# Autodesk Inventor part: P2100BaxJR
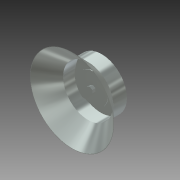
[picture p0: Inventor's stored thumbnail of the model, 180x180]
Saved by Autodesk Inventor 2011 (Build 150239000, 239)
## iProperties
Created: 2014-07
Part Number: P2100BaxJR
Document SubType Name: Modeling
Designer: Evgeny
Density: 1 g/cm^3
Author: Evgeny
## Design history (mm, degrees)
sketch "Эскиз1"
  geometry: L1 (31, 26.833)-(31, -26.833); L2 (-31, -26.833)-(-31, 26.833); C1 r 1.35 at (15, -26); A1 r 41 centre (0, 0) between (31, 26.833) and (-31, 26.833); A2 r 41 centre (0, 0) between (-31, -26.833) and (31, -26.833); 1 further point
  constraints: 4 end point, 4 point on circle, 3 centre point, 1 coincident, 1 parallel
  dimensions: "d1" = 62 distance between parallel lines of L1 L2; "d2" = 31 distance from line of L2 point (0, 0); "d3" = 41 radius of A1; "d4" = 41 radius of A2; "d7" = 2.7 diameter of C1; "d9" = 26 vertical distance of point (0, 0) C1.centre; "d50" = 15 horizontal distance of C1.centre point (0, 0)
extrude "Выдавливание1" new body sketch "Эскиз1" distance "d10" = 1; taper "d11" = 0 deg
sketch "Эскиз2"
  geometry: C1 r 4 at (0, 0); A1 r 41 centre (0, 0) between (31, 26.833) and (-31, 26.833) reference
  constraints: 1 centre point, 1 coincident
  dimensions: "d12" = 8 diameter of C1
extrude "Выдавливание2" join sketch "Эскиз2" distance "d13" = 6; taper "d14" = 0 deg
sketch "Эскиз3"
  geometry: C1 r 4 at (0, 0) reference; C2 r 28 at (0, 0)
  constraints: 1 centre point, 1 coincident
  dimensions: "d15" = 56 diameter of C2
extrude "Выдавливание3" join sketch "Эскиз3" distance "d16" = 1; taper "d17" = 0 deg
sketch "Эскиз4"
  geometry: L1 (5.774, 0)-(2.887, -5); L2 (2.887, -5)-(-2.887, -5); L3 (-2.887, -5)-(-5.774, 0); L4 (-5.774, 0)-(-2.887, 5); L5 (-2.887, 5)-(2.887, 5); L6 (2.887, 5)-(5.774, 0); C1 r 28 at (0, 0) reference; 1 further point
  constraints: 12 end point, 1 coincident, 13 other
  dimensions: "d18" = 10 distance between parallel lines of L2 L5
extrude "Выдавливание4" join sketch "Эскиз4" distance "d19" = 6; taper "d20" = 0 deg
sketch "Эскиз5"
  geometry: C1 r 4 at (0, 0); A1 r 41 centre (0, 0) between (31, 26.833) and (-31, 26.833) reference
  constraints: 1 centre point, 1 coincident
  dimensions: "d21" = 8 diameter of C1
extrude "Выдавливание5" join sketch "Эскиз5" distance "d22" = 7; taper "d23" = 0 deg
sketch "Эскиз6"
  geometry: C1 r 4 at (0, 0) reference; C2 r 47.5 at (0, 0); C3 r 4 at (-15, -26)
  constraints: 2 centre point, 1 coincident
  dimensions: "d24" = 95 diameter of C2; "d33" = 8 diameter of C3; "d52" = 26 vertical distance of C1.centre C3.centre; "d53" = 15 horizontal distance of C1.centre C3.centre
extrude "Выдавливание11" join sketch "Эскиз6" distance "d38" = 1.5; taper "d39" = 0 deg
sketch "Эскиз9"
  geometry: L1 (5.774, 0)-(2.887, -5); L2 (2.887, -5)-(-2.887, -5); L3 (-2.887, -5)-(-5.774, 0); L4 (-5.774, 0)-(-2.887, 5); L5 (-2.887, 5)-(2.887, 5); L6 (2.887, 5)-(5.774, 0); C1 r 47.5 at (0, 0) reference; 1 further point
  constraints: 12 end point, 1 coincident, 13 other
  dimensions: "d40" = 10 distance between parallel lines of L2 L5
extrude "Выдавливание12" join sketch "Эскиз9" distance "d41" = 6; taper "d42" = 0 deg
sketch "Эскиз10"
  geometry: C1 r 3 at (0, 0); 1 further point
  constraints: 1 centre point, 1 coincident
  dimensions: "d43" = 6 diameter of C1
extrude "Выдавливание13" join sketch "Эскиз10" distance "d44" = 6; taper "d45" = 0 deg
extrude "Выдавливание14" join sketch "Эскиз1" distance "d46" = 2; taper "d48" = 0 deg; dims "d47" = 8.5, "d49" = 0
sketch "Эскиз11"
  geometry: C1 r 47.5 at (0, 0) reference; C2 r 4 at (0, 0) reference; C3 r 47 at (0, 0)
  constraints: 1 centre point, 1 coincident
  dimensions: "d54" = 94 diameter of C3
extrude "Выдавливание15" join sketch "Эскиз11" distance "d55" = 24; taper "d56" = 0 deg
sketch "Эскиз12"
  geometry: L1 (-46.781, 17)-(-77.781, 47); L2 (-77.781, 47)-(-78.5, 47); L3 (-78.5, 47)-(-47.5, 17); L4 (-47.5, 17)-(-46.781, 17); L5 (0, -34)-(0, 60.5) reference; 1 further point
  constraints: 8 end point, 2 parallel, 1 horizontal
  dimensions: "d59" = 30 distance between parallel lines of L2 L4; "d60" = 17 distance from line of L4 point (0, 0); "d61" = 47.5 horizontal distance of point (0, 0) L3.end; "d62" = 31 horizontal distance of L1.end L1.start; "d63" = 0.5 distance between parallel lines of L1 L3
revolve "Вращение1" sketch "Эскиз12" stored, may be unused: angle "d64" = 90 deg
node "Твердое тело1"
other parameters: "d0" = 82
